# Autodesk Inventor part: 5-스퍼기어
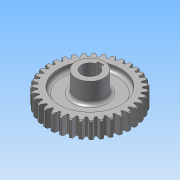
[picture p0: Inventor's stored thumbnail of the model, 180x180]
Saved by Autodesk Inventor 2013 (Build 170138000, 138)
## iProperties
Created: 2013-08
Part Number: 5-스퍼기어
Material: 강
Document SubType Name: Modeling
Designer: 한국산업디자인학원
Categories: <?xml version="1.0" encoding="UTF-16"?> <MemberInstance><Categories><FamilyTemplate><FamilyTemplateParameter ValueType="xs:double" Id="1" ObjectReferenceKey="da
Density: 1 g/cm^3
CustomPartVersion: 1
Author: 한국산업디자인학원
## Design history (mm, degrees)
sketch "Sketch1"
  geometry: C1 r 37 at (0, 0)
  constraints: 1 centre point
  dimensions: "d0" = 74 diameter of C1 (= da_da)
extrude "Extrusion1" new body sketch "Sketch1" distance "d1" = 15 (= da_b); taper "d2" = 0 deg
chamfer "모따기1" distance "d49" = 1; stored, may be unused: second distance "d50" = 2, angle "d51" = 45 deg
workplane "Work Plane2"
feature "피치 지름" dims "d4" = 10, "d5" = 0
workplane "Work Plane8"
workplane "Work Plane9"
feature "스퍼 기어" dims "da_b" = 15, "da_d" = 70, "da_aw" = 70, "da_da" = 74, "da_df" = 65, "da_dw" = 70, angle "da_beta" = 0 deg, "da_lefttooth" = 0, "da_righttooth" = 0
node "작업 평면11"
sketch "스케치4"
  geometry: C1 r 12.5 at (0, 0); 1 further point
  constraints: 1 centre point, 1 coincident
  dimensions: "d58" = 25 diameter of C1
extrude "돌출3" join sketch "스케치4" distance "d60" = 31; taper "d61" = 0 deg
sketch "스케치3"
  geometry: C1 r 27.5 at (0, 0); C2 r 12.5 at (0, 0); A1 r 36 centre (0, 0) between (-5.215, 35.62) and (-7.633, 35.181) reference
  constraints: 2 centre point, 2 coincident
  dimensions: "d52" = 55 diameter of C1; "d54" = 25 diameter of C2
extrude "돌출2" cut sketch "스케치3" distance "d55" = 5; taper "d56" = 0 deg
node "작업 평면12"
sketch "스케치5"
  geometry: L1 (-2.5, 7.071)-(-2.5, 9.8); L2 (-2.5, 9.8)-(2.5, 9.8); L3 (2.5, 9.8)-(2.5, 7.071); C1 r 12.5 at (0, 0) reference; A1 r 7.5 centre (0, 0) between (-2.5, 7.071) and (2.5, 7.071)
  constraints: 6 end point, 2 parallel, 2 point on circle, 1 centre point, 1 coincident, 1 perpendicular, 1 vertical
  dimensions: "d62" = 15 diameter of A1; "d64" = 17.3 dimension on A1 L2; "d65" = 5 distance of L1.end L2.end
extrude "돌출4" cut sketch "스케치5" stored distance "d66" = 31; taper "d67" = 0 deg
fillet "모깎기1" dims "d68" = 3
body "Solid1"
mirror "대칭1"
sketch "Sketch2"
  geometry: C1 r 37 at (0, 0) reference; C2 r 35 at (0, 0)
  constraints: 1 centre point, 1 coincident
  dimensions: "d3" = 70 diameter of C2 (= da_dw)
body "Srf1"
other parameters: "d17" = 0, "d34" = 0.8976 (computed from da_z), "d39" = 0, "d41" = 0, "d47" = 0, "d48" = 0, "d57" = 3
